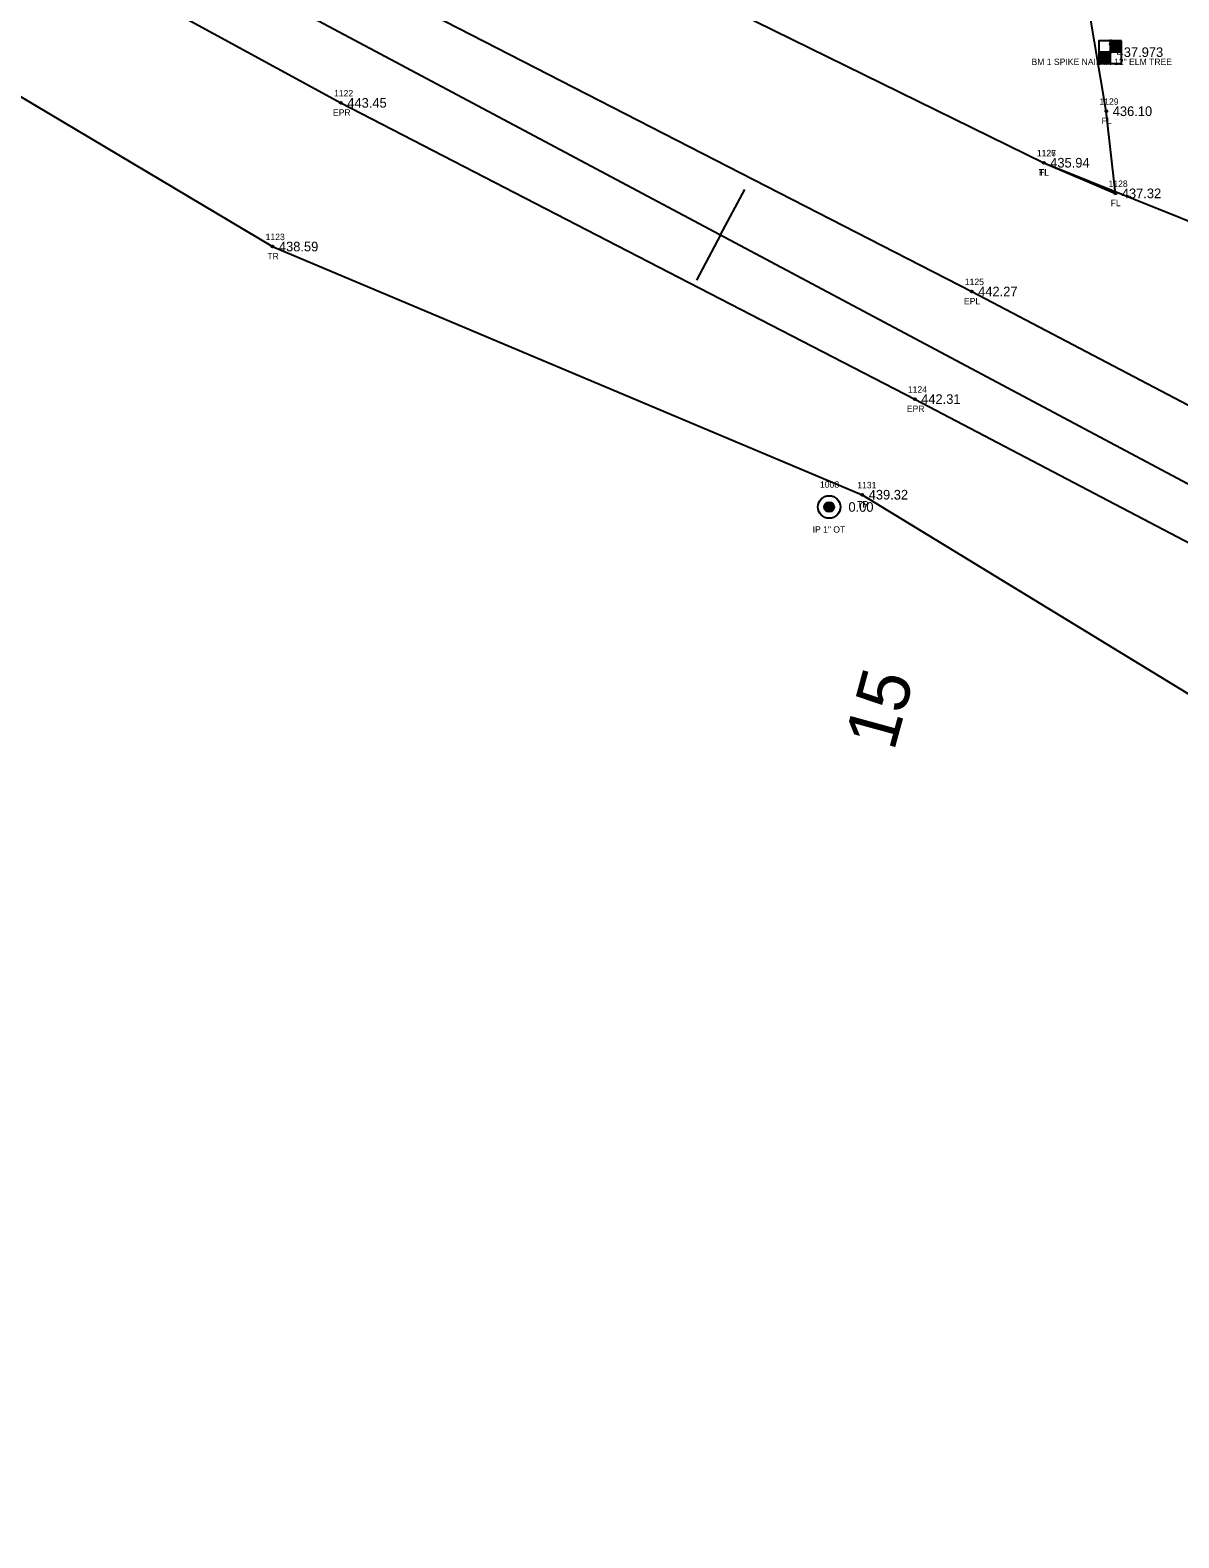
# Model space of a CAD drawing. Extents: x 1809463 to 1812121, y 790645 to 791946.
# Drawn here: x 1810532.5 to 1810711.3, y 791157.1 to 791391.9 of the extents above; entities that cross this region are included whole.
import ezdxf

# ---------------------------------------------------------------- set-up
doc = ezdxf.new("R2010")
doc.units = 0
for name, color, linetype in [('RD_EX_DV_Prop_txCode', 7, 'Continuous'), ('RD_EX_DV_PropPin', 7, 'Continuous'), ('RD_EX_Fence_Other', 7, 'Continuous'), ('RD_EX_Fence_Other_txCode', 7, 'Continuous'), ('RD_EX_Road', 7, 'Continuous'), ('RD_EX_Road_txCode', 7, 'Continuous'), ('RD_EX_TX_DV_Prop_ELEV', 7, 'Continuous'), ('RD_EX_TX_Fence_Other_ELEV', 7, 'Continuous'), ('RD_EX_TX_Road_ELEV', 7, 'Continuous'), ('RD_EX_TX_VEG_ELEV', 7, 'Continuous'), ('RD_EX_VEG', 7, 'Continuous'), ('RD_EX_VEG_txCode', 7, 'Continuous'), ('RD_HC_Cl', 7, 'Continuous'), ('RD_HC_Data_Tic', 7, 'Continuous'), ('RD_HC_Survey', 7, 'Continuous'), ('RD_HC_Survey_ELEV', 7, 'Continuous'), ('RD_HC_Survey_txCode', 7, 'Continuous'), ('RD_HC_TX_Sta50', 7, 'Continuous'), ('RD_SMD_Locator', 7, 'Continuous')]:
    doc.layers.add(name, color=color, linetype=linetype)

msp = doc.modelspace()

# ---------------------------------------------------------------- linework, layer by layer
at = {"layer": 'RD_EX_DV_PropPin'}
for p, q in [((1810656.15, 791317.44), (1810656.15, 791317.83)), ((1810656.18, 791317.34), (1810656.18, 791317.93)), ((1810656.22, 791317.26), (1810656.22, 791318)), ((1810656.25, 791317.21), (1810656.25, 791318.06)), ((1810656.29, 791317.16), (1810656.29, 791318.11)), ((1810656.32, 791317.12), (1810656.32, 791318.15)), ((1810656.36, 791317.08), (1810656.36, 791318.18)), ((1810656.39, 791317.05), (1810656.39, 791318.22)), ((1810656.43, 791317.02), (1810656.43, 791318.24)), ((1810656.46, 791317), (1810656.46, 791318.27)), ((1810656.5, 791316.98), (1810656.5, 791318.29)), ((1810656.53, 791316.96), (1810656.53, 791318.31)), ((1810656.57, 791316.94), (1810656.57, 791318.33)), ((1810656.6, 791316.93), (1810656.6, 791318.34)), ((1810656.64, 791316.91), (1810656.64, 791318.35)), ((1810656.67, 791316.9), (1810656.67, 791318.36)), ((1810656.71, 791316.89), (1810656.71, 791318.37)), ((1810656.74, 791316.89), (1810656.74, 791318.38)), ((1810656.78, 791316.88), (1810656.78, 791318.39)), ((1810656.81, 791316.88), (1810656.81, 791318.39)), ((1810656.85, 791316.87), (1810656.85, 791318.39)), ((1810656.88, 791316.87), (1810656.88, 791318.39)), ((1810656.92, 791316.87), (1810656.92, 791318.39)), ((1810656.96, 791316.88), (1810656.96, 791318.39)), ((1810656.99, 791316.88), (1810656.99, 791318.39)), ((1810657.03, 791316.89), (1810657.03, 791318.38)), ((1810657.06, 791316.89), (1810657.06, 791318.37)), ((1810657.1, 791316.9), (1810657.1, 791318.36)), ((1810657.13, 791316.91), (1810657.13, 791318.35)), ((1810657.17, 791316.93), (1810657.17, 791318.34)), ((1810657.2, 791316.94), (1810657.2, 791318.33)), ((1810657.24, 791316.96), (1810657.24, 791318.31)), ((1810657.27, 791316.98), (1810657.27, 791318.29)), ((1810657.31, 791317), (1810657.31, 791318.27)), ((1810657.34, 791317.02), (1810657.34, 791318.24)), ((1810657.38, 791317.05), (1810657.38, 791318.22)), ((1810657.41, 791317.08), (1810657.41, 791318.18)), ((1810657.45, 791317.12), (1810657.45, 791318.15)), ((1810657.48, 791317.16), (1810657.48, 791318.11)), ((1810657.52, 791317.21), (1810657.52, 791318.06)), ((1810657.55, 791317.26), (1810657.55, 791318)), ((1810657.59, 791317.34), (1810657.59, 791317.93)), ((1810657.62, 791317.44), (1810657.62, 791317.83))]:
    msp.add_line(p, q, dxfattribs=at)
for radius in [1.75, 0.761]:
    msp.add_circle((1810656.88, 791317.63), radius, dxfattribs=at)
at = {"layer": 'RD_EX_Fence_Other'}
msp.add_lwpolyline([(1810448.73, 791529.58), (1810441.83, 791495.45), (1810510.46, 791460.36), (1810597.87, 791416.6), (1810690.3, 791371.23), (1810701.45, 791366.46), (1810700.04, 791379.25), (1810697.34, 791395.29)], dxfattribs=at)
at = {"layer": 'RD_EX_Road'}
for points in [[(1810147.3, 791633.32), (1810235.73, 791586.37), (1810316.89, 791542.45), (1810324.32, 791538.42), (1810350.04, 791524.6), (1810412.94, 791490.75), (1810461.45, 791466.07), (1810501.18, 791444.55), (1810589.18, 791397.37), (1810679.08, 791351.18), (1810768.4, 791304.34)], [(1810138.18, 791616.8), (1810226.92, 791569.59), (1810315.11, 791521.87), (1810404.37, 791475.11), (1810492.73, 791428.56), (1810580.86, 791380.55), (1810670.21, 791334.43), (1810759.54, 791287.61)]]:
    msp.add_lwpolyline(points, dxfattribs=at)
at = {"layer": 'RD_EX_VEG'}
for points in [[(1810130.25, 791598.81), (1810215.39, 791551.2), (1810300.2, 791497.21), (1810388.33, 791446.45), (1810482.97, 791410.13), (1810570.21, 791358.18), (1810662.04, 791319.54), (1810748.52, 791266.73), (1810838.03, 791232.12), (1810883.83, 791207.75), (1810930.73, 791188.17), (1810978.23, 791166.26), (1811026.78, 791154.63), (1811075.78, 791136.08), (1811111.46, 791120.38), (1811106.22, 791101.92)], [(1810341.02, 791567.09), (1810359.88, 791551.99), (1810422.51, 791511.77), (1810509.88, 791459.82), (1810597.87, 791416.6), (1810690.3, 791371.23), (1810825.66, 791316.88), (1810866.79, 791289.5), (1810909.83, 791263.61), (1810951.77, 791236.76), (1810996.45, 791220.63), (1811044.92, 791210.53), (1811089.45, 791196.27), (1811139.01, 791190.33), (1811186.69, 791184.29), (1811236.76, 791180.63), (1811249.82, 791178.89), (1811262.54, 791198.89)]]:
    msp.add_lwpolyline(points, dxfattribs=at)
at = {"layer": 'RD_HC_Cl'}
msp.add_line((1810106.46, 791644.15), (1810813.4, 791267.65), dxfattribs=at)
at = {"layer": 'RD_HC_Data_Tic'}
for q in [(1810643.75, 791367.06), (1810636.23, 791352.94)]:
    msp.add_line((1810639.99, 791360), q, dxfattribs=at)
at = {"layer": 'RD_HC_Survey'}
for p, q in [((1810702.39, 791388.44), (1810698.89, 791388.44)), ((1810698.89, 791388.44), (1810698.89, 791386.69)), ((1810698.91, 791388.44), (1810698.91, 791386.69)), ((1810698.94, 791388.44), (1810698.94, 791386.69)), ((1810698.96, 791388.44), (1810698.96, 791386.69)), ((1810698.98, 791388.44), (1810698.98, 791386.69)), ((1810699.01, 791388.44), (1810699.01, 791386.69)), ((1810699.03, 791388.44), (1810699.03, 791386.69)), ((1810699.06, 791388.44), (1810699.06, 791386.69)), ((1810699.08, 791388.44), (1810699.08, 791386.69)), ((1810699.11, 791388.44), (1810699.11, 791386.69)), ((1810699.13, 791388.44), (1810699.13, 791386.69)), ((1810699.16, 791388.44), (1810699.16, 791386.69)), ((1810699.18, 791388.44), (1810699.18, 791386.69)), ((1810699.21, 791388.44), (1810699.21, 791386.69)), ((1810699.23, 791388.44), (1810699.23, 791386.69)), ((1810699.26, 791388.44), (1810699.26, 791386.69)), ((1810699.28, 791388.44), (1810699.28, 791386.69)), ((1810699.31, 791388.44), (1810699.31, 791386.69)), ((1810699.33, 791388.44), (1810699.33, 791386.69)), ((1810699.36, 791388.44), (1810699.36, 791386.69)), ((1810699.38, 791388.44), (1810699.38, 791386.69)), ((1810699.41, 791388.44), (1810699.41, 791386.69)), ((1810699.43, 791388.44), (1810699.43, 791386.69)), ((1810699.46, 791388.44), (1810699.46, 791386.69)), ((1810699.48, 791388.44), (1810699.48, 791386.69)), ((1810699.5, 791388.44), (1810699.5, 791386.69)), ((1810699.53, 791388.44), (1810699.53, 791386.69)), ((1810699.55, 791388.44), (1810699.55, 791386.69)), ((1810699.58, 791388.44), (1810699.58, 791386.69)), ((1810699.6, 791388.44), (1810699.6, 791386.69)), ((1810699.63, 791388.44), (1810699.63, 791386.69)), ((1810699.65, 791388.44), (1810699.65, 791386.69)), ((1810699.68, 791388.44), (1810699.68, 791386.69)), ((1810699.7, 791388.44), (1810699.7, 791386.69)), ((1810699.73, 791388.44), (1810699.73, 791386.69)), ((1810699.75, 791388.44), (1810699.75, 791386.69)), ((1810699.78, 791388.44), (1810699.78, 791386.69)), ((1810699.8, 791388.44), (1810699.8, 791386.69)), ((1810699.83, 791388.44), (1810699.83, 791386.69)), ((1810699.85, 791388.44), (1810699.85, 791386.69)), ((1810699.88, 791388.44), (1810699.88, 791386.69)), ((1810699.9, 791388.44), (1810699.9, 791386.69)), ((1810699.93, 791388.44), (1810699.93, 791386.69)), ((1810699.95, 791388.44), (1810699.95, 791386.69)), ((1810699.97, 791388.44), (1810699.97, 791386.69)), ((1810700, 791388.44), (1810700, 791386.69)), ((1810700.02, 791388.44), (1810700.02, 791386.69)), ((1810700.05, 791388.44), (1810700.05, 791386.69)), ((1810700.07, 791388.44), (1810700.07, 791386.69)), ((1810700.1, 791388.44), (1810700.1, 791386.69)), ((1810700.12, 791388.44), (1810700.12, 791386.69)), ((1810700.15, 791388.44), (1810700.15, 791386.69)), ((1810700.17, 791388.44), (1810700.17, 791386.69)), ((1810700.2, 791388.44), (1810700.2, 791386.69)), ((1810700.22, 791388.44), (1810700.22, 791386.69)), ((1810700.25, 791388.44), (1810700.25, 791386.69)), ((1810700.27, 791388.44), (1810700.27, 791386.69)), ((1810700.3, 791388.44), (1810700.3, 791386.69)), ((1810700.32, 791388.44), (1810700.32, 791386.69)), ((1810700.35, 791388.44), (1810700.35, 791386.69)), ((1810700.37, 791388.44), (1810700.37, 791386.69)), ((1810700.4, 791388.44), (1810700.4, 791386.69)), ((1810700.42, 791388.44), (1810700.42, 791386.69)), ((1810700.45, 791388.44), (1810700.45, 791386.69)), ((1810700.47, 791388.44), (1810700.47, 791386.69)), ((1810700.49, 791388.44), (1810700.49, 791386.69)), ((1810700.52, 791388.44), (1810700.52, 791386.69)), ((1810700.54, 791388.44), (1810700.54, 791386.69)), ((1810700.57, 791388.44), (1810700.57, 791386.69)), ((1810700.59, 791388.44), (1810700.59, 791386.69)), ((1810700.62, 791388.44), (1810700.62, 791386.69)), ((1810700.64, 791390.19), (1810700.64, 791386.69)), ((1810700.65, 791390.19), (1810700.65, 791388.44)), ((1810700.68, 791390.19), (1810700.68, 791388.44)), ((1810700.7, 791390.19), (1810700.7, 791388.44)), ((1810700.73, 791390.19), (1810700.73, 791388.44)), ((1810700.75, 791390.19), (1810700.75, 791388.44)), ((1810700.78, 791390.19), (1810700.78, 791388.44)), ((1810700.8, 791390.19), (1810700.8, 791388.44)), ((1810700.83, 791390.19), (1810700.83, 791388.44)), ((1810700.85, 791390.19), (1810700.85, 791388.44)), ((1810700.88, 791390.19), (1810700.88, 791388.44)), ((1810700.9, 791390.19), (1810700.9, 791388.44)), ((1810700.93, 791390.19), (1810700.93, 791388.44)), ((1810700.95, 791390.19), (1810700.95, 791388.44)), ((1810700.98, 791390.19), (1810700.98, 791388.44)), ((1810701, 791390.19), (1810701, 791388.44)), ((1810701.02, 791390.19), (1810701.02, 791388.44)), ((1810701.05, 791390.19), (1810701.05, 791388.44)), ((1810701.07, 791390.19), (1810701.07, 791388.44)), ((1810701.1, 791390.19), (1810701.1, 791388.44)), ((1810701.12, 791390.19), (1810701.12, 791388.44)), ((1810701.15, 791390.19), (1810701.15, 791388.44)), ((1810701.17, 791390.19), (1810701.17, 791388.44)), ((1810701.2, 791390.19), (1810701.2, 791388.44)), ((1810701.22, 791390.19), (1810701.22, 791388.44)), ((1810701.25, 791390.19), (1810701.25, 791388.44)), ((1810701.27, 791390.19), (1810701.27, 791388.44)), ((1810701.3, 791390.19), (1810701.3, 791388.44)), ((1810701.32, 791390.19), (1810701.32, 791388.44)), ((1810701.35, 791390.19), (1810701.35, 791388.44)), ((1810701.37, 791390.19), (1810701.37, 791388.44)), ((1810701.4, 791390.19), (1810701.4, 791388.44)), ((1810701.42, 791390.19), (1810701.42, 791388.44)), ((1810701.45, 791390.19), (1810701.45, 791388.44)), ((1810701.47, 791390.19), (1810701.47, 791388.44)), ((1810701.49, 791390.19), (1810701.49, 791388.44)), ((1810701.52, 791390.19), (1810701.52, 791388.44)), ((1810701.54, 791390.19), (1810701.54, 791388.44)), ((1810701.57, 791390.19), (1810701.57, 791388.44)), ((1810701.59, 791390.19), (1810701.59, 791388.44)), ((1810701.62, 791390.19), (1810701.62, 791388.44)), ((1810701.64, 791390.19), (1810701.64, 791388.44)), ((1810701.67, 791390.19), (1810701.67, 791388.44)), ((1810701.69, 791390.19), (1810701.69, 791388.44)), ((1810701.72, 791390.19), (1810701.72, 791388.44)), ((1810701.74, 791390.19), (1810701.74, 791388.44)), ((1810701.77, 791390.19), (1810701.77, 791388.44)), ((1810701.79, 791390.19), (1810701.79, 791388.44)), ((1810701.82, 791390.19), (1810701.82, 791388.44)), ((1810701.84, 791390.19), (1810701.84, 791388.44)), ((1810701.87, 791390.19), (1810701.87, 791388.44)), ((1810701.89, 791390.19), (1810701.89, 791388.44)), ((1810701.92, 791390.19), (1810701.92, 791388.44)), ((1810701.94, 791390.19), (1810701.94, 791388.44)), ((1810701.97, 791390.19), (1810701.97, 791388.44)), ((1810701.99, 791390.19), (1810701.99, 791388.44)), ((1810702.01, 791390.19), (1810702.01, 791388.44)), ((1810702.04, 791390.19), (1810702.04, 791388.44)), ((1810702.06, 791390.19), (1810702.06, 791388.44)), ((1810702.09, 791390.19), (1810702.09, 791388.44)), ((1810702.11, 791390.19), (1810702.11, 791388.44)), ((1810702.14, 791390.19), (1810702.14, 791388.44)), ((1810702.16, 791390.19), (1810702.16, 791388.44)), ((1810702.19, 791390.19), (1810702.19, 791388.44)), ((1810702.21, 791390.19), (1810702.21, 791388.44)), ((1810702.24, 791390.19), (1810702.24, 791388.44)), ((1810702.26, 791390.19), (1810702.26, 791388.44)), ((1810702.29, 791390.19), (1810702.29, 791388.44)), ((1810702.31, 791390.19), (1810702.31, 791388.44)), ((1810702.34, 791390.19), (1810702.34, 791388.44)), ((1810702.36, 791390.19), (1810702.36, 791388.44))]:
    msp.add_line(p, q, dxfattribs=at)
msp.add_lwpolyline([(1810702.39, 791390.19), (1810698.89, 791390.19), (1810698.89, 791386.69), (1810702.39, 791386.69)], close=True, dxfattribs=at)
at = {"layer": 'RD_SMD_Locator'}
for centre in [(1810700.64, 791388.44), (1810580.86, 791380.55), (1810700.04, 791379.25), (1810690.3, 791371.23), (1810690.3, 791371.23), (1810701.45, 791366.46), (1810570.21, 791358.18), (1810679.08, 791351.18), (1810670.21, 791334.43), (1810656.88, 791317.63), (1810662.04, 791319.54)]:
    msp.add_circle(centre, 0.15, dxfattribs=at)

# ---------------------------------------------------------------- texts
at = {"layer": 'RD_EX_DV_Prop_txCode'}
for s, p in [('1008', (1810655.46, 791320.63)), ('IP 1" OT', (1810654.31, 791313.63))]:
    msp.add_text(s, height=1, dxfattribs=at).set_placement(p)
at = {"layer": 'RD_EX_Fence_Other_txCode'}
for s, p in [('1129', (1810698.97, 791380.25)), ('FL', (1810699.31, 791377.25)), ('1126', (1810689.21, 791372.23)), ('FL', (1810689.57, 791369.23)), ('1128', (1810700.39, 791367.46)), ('FL', (1810700.72, 791364.46))]:
    msp.add_text(s, height=1, dxfattribs=at).set_placement(p)
at = {"layer": 'RD_EX_Road_txCode'}
for s, p in [('1122', (1810579.8, 791381.55)), ('EPR', (1810579.63, 791378.55)), ('1125', (1810678.01, 791352.18)), ('EPL', (1810677.87, 791349.18)), ('1124', (1810669.14, 791335.43)), ('EPR', (1810668.98, 791332.43))]:
    msp.add_text(s, height=1, dxfattribs=at).set_placement(p)
at = {"layer": 'RD_EX_TX_DV_Prop_ELEV'}
msp.add_text('0.00', height=1.5, dxfattribs=at).set_placement((1810659.89, 791316.88))
at = {"layer": 'RD_EX_TX_Fence_Other_ELEV'}
for s, p in [('436.10', (1810701.04, 791378.5)), ('435.94', (1810691.3, 791370.48)), ('437.32', (1810702.45, 791365.71))]:
    msp.add_text(s, height=1.5, dxfattribs=at).set_placement(p)
at = {"layer": 'RD_EX_TX_Road_ELEV'}
for s, p in [('443.45', (1810581.86, 791379.8)), ('442.27', (1810680.08, 791350.43)), ('442.31', (1810671.21, 791333.68))]:
    msp.add_text(s, height=1.5, dxfattribs=at).set_placement(p)
at = {"layer": 'RD_EX_TX_VEG_ELEV'}
for s, p in [('435.94', (1810691.3, 791370.48)), ('438.59', (1810571.21, 791357.43)), ('439.32', (1810663.04, 791318.79))]:
    msp.add_text(s, height=1.5, dxfattribs=at).set_placement(p)
at = {"layer": 'RD_EX_VEG_txCode'}
for s, p in [('1127', (1810689.24, 791372.23)), ('TL', (1810689.53, 791369.23)), ('1123', (1810569.15, 791359.18)), ('TR', (1810569.42, 791356.18)), ('1131', (1810661.26, 791320.54)), ('TR', (1810661.24, 791317.54))]:
    msp.add_text(s, height=1, dxfattribs=at).set_placement(p)
at = {"layer": 'RD_HC_Survey_ELEV'}
msp.add_text('437.973', height=1.5, dxfattribs=at).set_placement((1810701.64, 791387.69))
at = {"layer": 'RD_HC_Survey_txCode'}
for s, p in [('8', (1810700.35, 791389.44)), ('BM 1 SPIKE NAIL IN 12" ELM TREE', (1810688.39, 791386.44))]:
    msp.add_text(s, height=1, dxfattribs=at).set_placement(p)
at = {"layer": 'RD_HC_TX_Sta50'}
msp.add_text('15', height=8, rotation=74.6948, dxfattribs=at).set_placement((1810666.96, 791279.47))

doc.saveas('drawing.dxf')
